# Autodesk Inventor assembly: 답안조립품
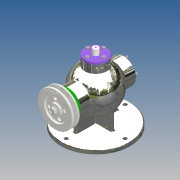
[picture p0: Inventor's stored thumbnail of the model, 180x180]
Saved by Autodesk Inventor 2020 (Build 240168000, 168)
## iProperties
Created: 2020-08
Part Number: 답안조립품
Document SubType Name: Assembly
Designer: EZDESIGN
Author: EZDESIGN
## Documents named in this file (18)
- C:\Users\EZDESIGN\Desktop\700806V1019\답안조립품.iam
- C:\Users\EZDESIGN\Desktop\700806V1019\본체.ipt
- C:\Users\EZDESIGN\Desktop\700806V1019\베어링 6202.ipt
- 베어링 6202.ipt
- C:\Users\EZDESIGN\Desktop\700806V1019\멈춤링 35x1.6.ipt
- 멈춤링 35x1.6.ipt
- C:\Users\EZDESIGN\Desktop\700806V1019\뒤커버.ipt
- C:\Users\EZDESIGN\Desktop\700806V1019\편심축.ipt
- C:\Users\EZDESIGN\Desktop\700806V1019\멈춤링 15x1.ipt
- C:\Users\EZDESIGN\Desktop\700806V1019\칼라.ipt
- C:\Users\EZDESIGN\Desktop\700806V1019\앞커버.ipt
- C:\Users\EZDESIGN\Desktop\700806V1019\볼트 M4.ipt
- C:\Users\EZDESIGN\Desktop\700806V1019\V-벨트풀리.ipt
- C:\Users\EZDESIGN\Desktop\700806V1019\키 3x3x12.ipt
- C:\Users\EZDESIGN\Desktop\700806V1019\너트 M8.ipt
- C:\Users\EZDESIGN\Desktop\700806V1019\오일 실 15 30 7.ipt
- C:\Users\EZDESIGN\Desktop\700806V1019\슬라이드.ipt
- C:\Users\EZDESIGN\Desktop\700806V1019\상부커버.ipt
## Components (1 placed, 1 different names)
1. V-벨트풀리:1
